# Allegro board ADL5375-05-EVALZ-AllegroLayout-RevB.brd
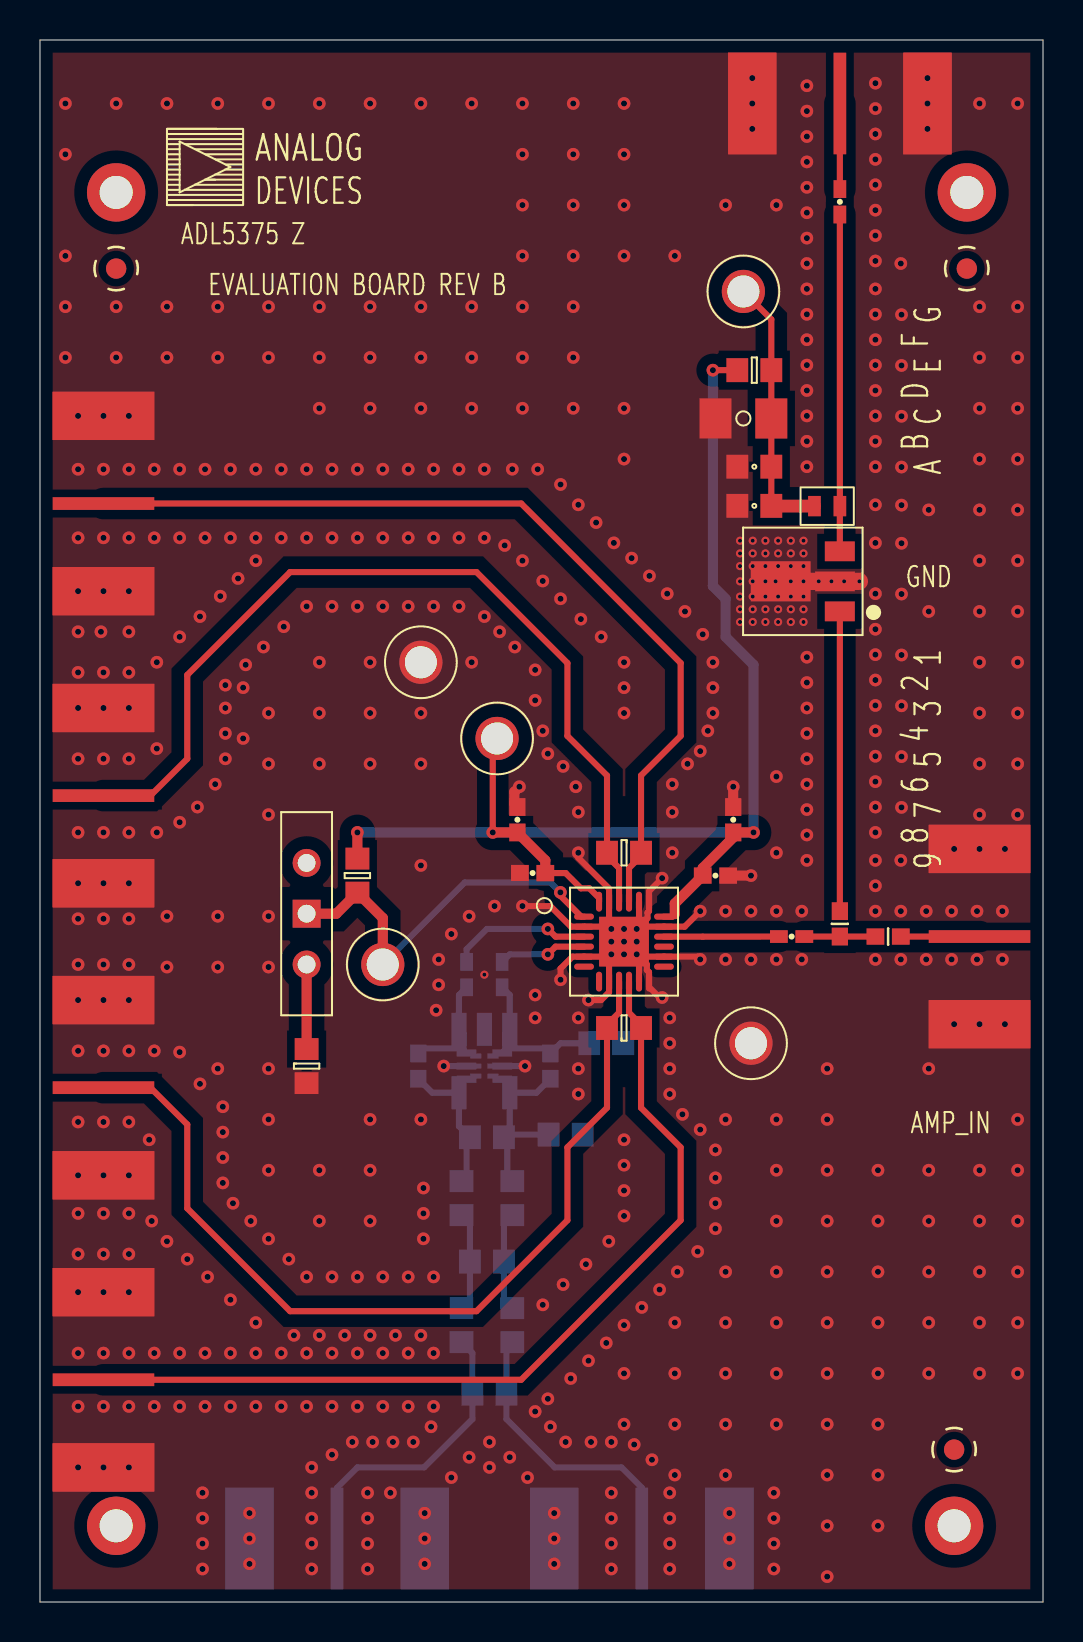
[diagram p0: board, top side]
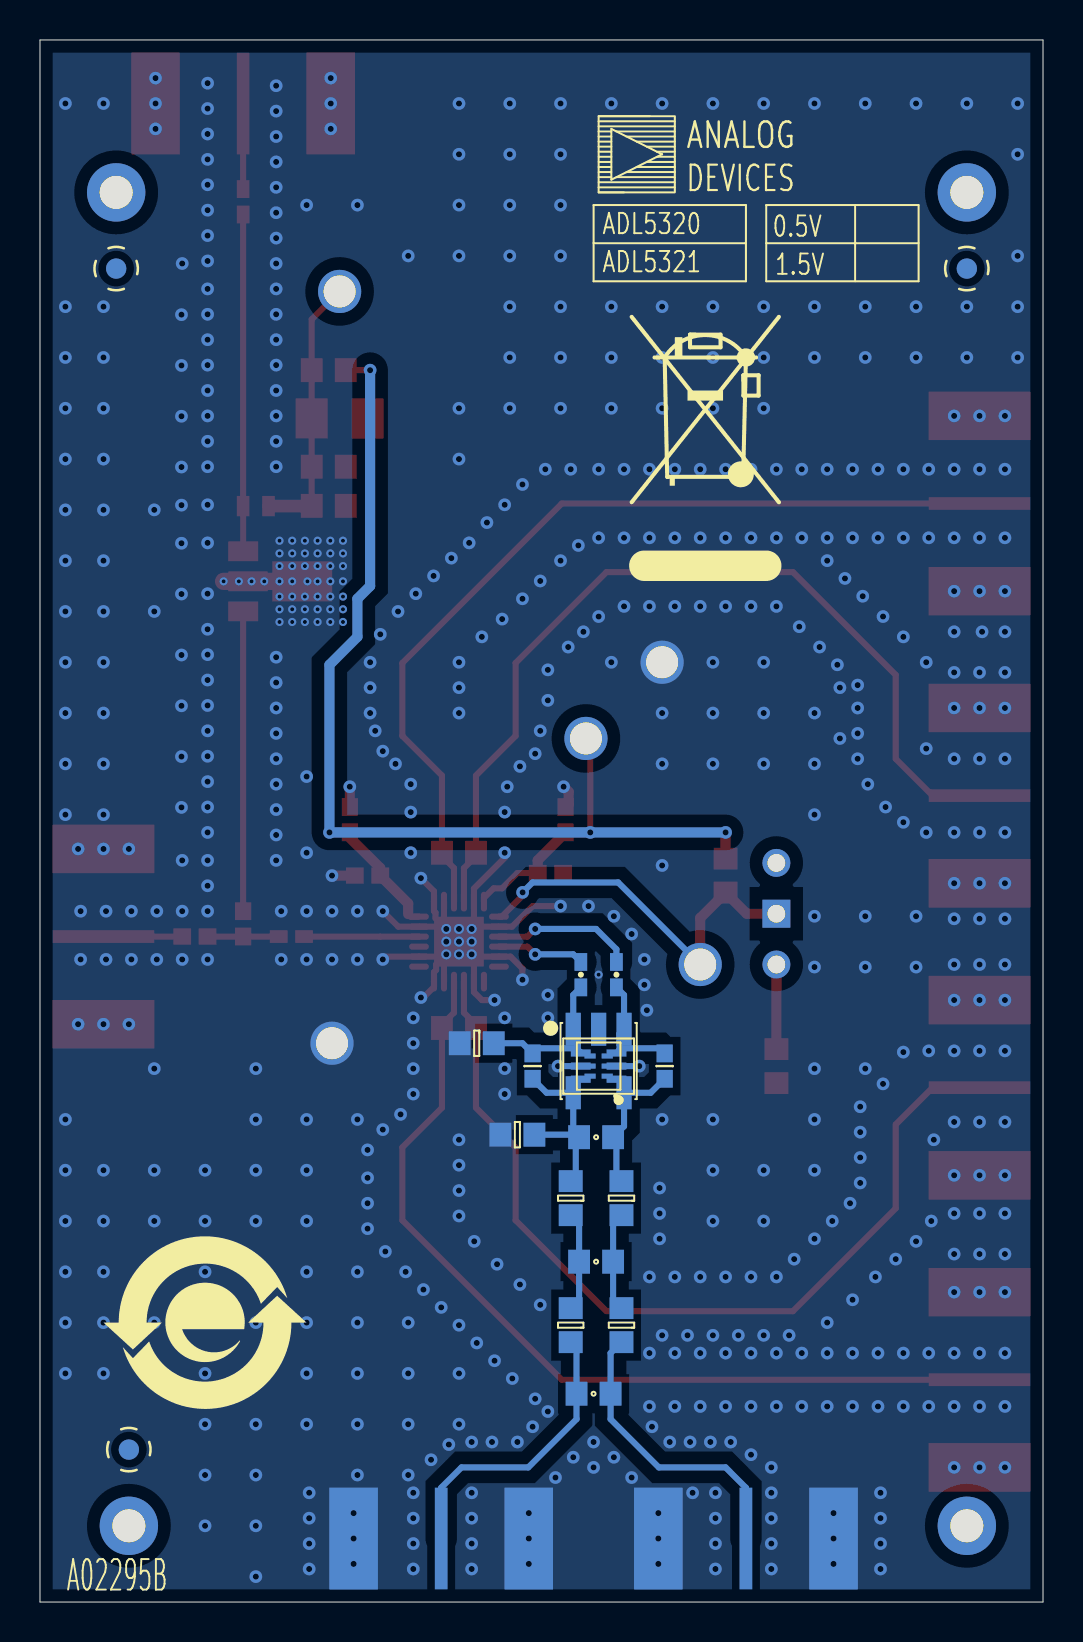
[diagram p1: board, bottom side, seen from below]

Outline 50.16 x 78.11 mm; copper layers: TOP, L2_GND, L3_GND, BOTTOM. Coordinates in mm from the lower left corner of the outline.
Outline path: 0,78.11 50.16,78.11 50.16,0 0,0 0,78.11

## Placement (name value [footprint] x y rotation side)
AMP_OUT  JOHNSON142-0701-851  [CNJOHNSON142-0701-851]  40 75.56 90 top
C1  100pF  [C0402]  37.59 33.27 0 top
C2  100pF  [C0402]  33.78 36.32 0 top
C3  100pF  [C0402]  24.64 36.45 180 top
C4  0.1UF  [C0402]  34.67 39.12 90 top
C5  0.1UF  [C0402]  23.88 39.12 90 top
C6  100pF  [C0402]  21.34 31.37 90 bottom
C7  100pF  [C0402]  23.11 31.37 90 bottom
C9  10UF  [C1206]  35.18 59.18 180 top
C10  10000pF  [C0603]  35.73 56.77 180 top
C11  22PF  [C0603]  35.73 54.81 180 top
C12  22PF  [C0402]  40 70.02 90 top
C16  TBD0603  [C0603]  22.35 23.24 0 bottom
C17  TBD0603  [C0603]  22.35 17.02 0 bottom
C18  TBD0603  [C0603]  22.48 10.41 0 bottom
DSOP  YEL  [CNLOOPTP]  17.15 31.88 90 top
GND  BLK  [CNLOOPTP]  19.05 46.99 0 top
GND1  BLK  [CNLOOPTP]  35.56 27.94 0 top
IBBN  JOHNSON142-0701-851  [CNJOHNSON142-0701-851]  2.54 40.32 180 top
IBBP  JOHNSON142-0701-851  [CNJOHNSON142-0701-851]  2.54 54.93 180 top
L1  15nH  [L7144]  39.37 54.8 180 top
LOIN  JOHNSON142-0701-851  [CNJOHNSON142-0701-851]  30.1 2.54 270 bottom
LOIP  JOHNSON142-0701-851  [CNJOHNSON142-0701-851]  14.86 2.54 270 bottom
MOD_OUT  JOHNSON142-0701-851  [CNJOHNSON142-0701-851]  47.62 33.27 0 top
NOREF  -  []  257.81 -31.75 0 top
NOREF#2  -  []  443.48 -203.84 0 top
NOREF#3  -  [unnamed#2]  3.81 66.67 0 top
NOREF#4  -  []  542.54 -186.06 0 top
NOREF#5  -  []  6.35 69.85 0 top
NOREF#6  -  []  -158.75 -118.11 0 top
NOREF#7  -  [unnamed#2]  45.72 3.81 0 top
NOREF#8  -  []  50.16 0 90 top
NOREF#9  -  [unnamed#2]  45.72 7.62 0 top
NOREF#10  -  []  0 0 0 top
NOREF#11  -  []  -158.75 -118.11 0 top
NOREF#12  -  []  0 78.11 270 top
NOREF#13  -  [unnamed#2]  46.35 66.67 0 top
NOREF#14  -  []  0 0 0 top
NOREF#15  -  []  0 0 90 top
NOREF#16  -  []  0 0 90 top
NOREF#17  -  []  0 0 0 top
NOREF#18  -  [unnamed#2]  3.81 70.48 0 top
NOREF#19  -  []  -171.2 -257.18 0 top
NOREF#20  -  []  192.79 -64.9 0 top
NOREF#21  -  [unnamed#2]  3.81 3.81 0 top
NOREF#22  -  []  26.67 85.09 0 top
NOREF#23  -  []  -41.91 -107.95 0 top
NOREF#24  -  []  50.16 78.11 180 top
NOREF#25  -  [unnamed#2]  46.35 70.48 0 top
NOREF#26  -  [unnamed#2]  46.35 66.67 180 bottom
NOREF#27  -  [unnamed#2]  3.81 66.67 180 bottom
NOREF#28  -  []  7.62 67.95 180 bottom
NOREF#29  -  [unnamed#2]  45.72 7.62 180 bottom
NOREF#30  -  []  22.23 70.48 180 bottom
NOREF#31  -  []  41.91 13.97 180 bottom
QBBN  JOHNSON142-0701-851  [CNJOHNSON142-0701-851]  2.54 25.72 180 top
QBBP  JOHNSON142-0701-851  [CNJOHNSON142-0701-851]  2.54 11.11 180 top
R1  TBD0402  [R0402]  42.42 33.27 0 top
R2  0  [R0402]  40 33.91 90 top
R6  10K  [R0603]  15.88 36.32 270 top
R7  100  [R0603]  29.21 37.47 180 top
R12  100  [R0603]  29.21 28.7 0 top
R13  0  [R0603]  35.73 61.59 180 top
R14  0  [R0603]  21.08 13.84 90 bottom
R15  49.9  [R0603]  13.33 26.8 270 top
R16  TBD0603  [R0603]  23.62 13.84 90 bottom
R17  0  [R0603]  28.32 27.94 0 bottom
R18  0  [R0603]  21.08 20.19 90 bottom
R19  TBD0603  [R0603]  23.62 20.19 90 bottom
R20  TBD0402  [R0402]  25.53 26.8 90 bottom
R21  0  [R0402]  18.92 26.8 90 bottom
R22  TBD0603  [R0603]  26.29 23.37 0 bottom
S1  09-03-201-02  [SWSECMA0903201]  13.33 34.42 90 top
T1  TC1-1-43A+  [AT224-1]  22.23 27.05 180 bottom
T2  3600BL14M050  [T0603-6P]  22.23 26.8 90 bottom
T2A  5400BL15B050E  [XFMR2450BL15B050]  22.23 26.8 90 bottom
U1  ADL5375-05ACPZ-R7  [QFN24_4X4_PAD2_5X2_5]  29.21 33.02 270 top
U2  ADL5320  [SOT-89]  38.15 51.04 90 top
VPOS  RED  [CNLOOPTP]  22.86 43.18 0 top
VPOS_AMP  RED  [CNLOOPTP]  35.18 65.53 0 top

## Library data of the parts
AMP_OUT IBBN IBBP LOIN LOIP MOD_OUT QBBN QBBP = CNBNC5P: User Part Number: UPN; part number: CNBNC5P_SM-JOHNSON142-0701-851,E000923,CNJOHNSON142-0701-851
C1-C3 C6 C7 = CAP: part number: CAP_SM-100PF,50V,5,E007896,C0402; tolerance: 5
C4 C5 = CAP: part number: CAP_SM-0.1UF,16V,10,E007200,C0402; tolerance: 10
C9 = CAP: Tolerance: 10; User Part Number: UPN; part number: CAP_SM-10UF,25V,10,E006874,C1206; tolerance: 10
C10 = CAP: Tolerance: 10; User Part Number: UPN; part number: CAP_SM-10000PF,25V,10,E012078,C0603; tolerance: 10
C11 = CAP: Tolerance: 5; User Part Number: UPN; part number: CAP_SM-22PF,50V,5,E000411,C0603; tolerance: 5
C12 = CAP: part number: CAP_SM-22PF,50V,5,E000265,C0402; tolerance: 5
C16-C18 = CAP: User Part Number: UPN; part number: CAP_SM-TBD0603,TBD0603,TBD0603,E000382,C0603
DSOP = CNTP1P: User Part Number: UPN; part number: CNTP1P_TH-YEL,E000945,CNLOOPTP
GND GND1 = CNTP1P: User Part Number: UPN; part number: CNTP1P_TH-BLK,E000948,CNLOOPTP
L1 = IND: Tolerance: 5; User Part Number: UPN; part number: IND_SM-15NH,5,E010518,L7144; tolerance: 5
R1 R20 = RES: User Part Number: UPN; part number: RES_SM-TBD0402,TBD0402,TBD0402,E004049,R0402
R2 R21 = RES: Tolerance: 5; User Part Number: UPN; part number: RES_SM-0,1/16W,5,E003438,R0402; tolerance: 5
R6 = RES: part number: RES_SM-10K,1/10W,1,E003671,R0603; tolerance: 1
R7 R12 = RES: part number: RES_SM-100,1/10W,1,E003668,R0603; tolerance: 1
R13 R14 R17 R18 = RES: Tolerance: 1; User Part Number: UPN; part number: RES_SM-0,1/16W,1,E004207,R0603; tolerance: 1
R15 = RES: part number: RES_SM-49.9,1/10W,1,E003673,R0603; tolerance: 1
R16 R19 R22 = RES: User Part Number: UPN; part number: RES_SM-TBD0603,TBD0603,TBD0603,E004050,R0603
S1 = SWSECMA: User Part Number: UPN; part number: SWSECMA_TH-09-03-201-02,E004565,SWSECMA0903201
T1 = XFMRETC1_A: User Part Number: UPN; part number: XFMRETC1_A_SM-TC1-1-43A+,E012306,AT224-1
T2 = XFMR3600BL: User Part Number: UPN; part number: XFMR3600BL_SM-3600BL14M050,E007972,T0603-6P
T2A = XFMR3600BL: User Part Number: UPN; part number: XFMR3600BL_SM-5400BL15B050E,E012539,XFMR2450BL15B050
U1 = ADL5375: User Part Number: UPN; part number: ADL5375_SM-ADL5375-05ACPZ-R7,E007336,QFN24_4X4_PAD2_5X2_5
U2 = ADL5320: User Part Number: UPN; part number: ADL5320_SM-ADL5320,E006429,SOT-89
VPOS VPOS_AMP = CNTP1P: User Part Number: UPN; part number: CNTP1P_TH-RED,E000947,CNLOOPTP

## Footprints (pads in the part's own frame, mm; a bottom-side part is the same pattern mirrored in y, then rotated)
AT224-1
  rect 0.762x1.651 smd: 1(-1.27,1.587) 2(0,1.587) 3(1.27,1.587) 4(1.27,-1.587) 6(-1.27,-1.587)
C0402
  rect 0.889x0.813 smd: 1(-0.635,0) 2(0.635,0)
C0603
  rect 1.092x1.194 smd: 1(-0.851,0) 2(0.851,0)
C1206
  rect 1.6x2.007 smd: 1(-1.397,0) 2(1.397,0)
CNJOHNSON142-0701-851
  rect 5.08x0.635 smd: 1(-0.635,0)
  rect 5.08x2.413 smd: 2(-0.635,4.381) 3(-0.635,4.381) 4(-0.635,-4.381) 5(-0.635,-4.381)
CNLOOPTP
  round 2.159 hole 1.6: 1(0,0)
L7144
  rect 0.635x1.016 smd: 1(-0.635,0) 2(0.635,0)
QFN24_4X4_PAD2_5X2_5
  oval 0.305x0.991 smd: 1(-1.25,-1.999) 2(-0.749,-1.999) 3(-0.249,-1.999) 4(0.249,-1.999) 5(0.749,-1.999) 6(1.25,-1.999) 13(1.25,1.999) 14(0.749,1.999) 15(0.249,1.999) 16(-0.249,1.999) 17(-0.749,1.999) 18(-1.25,1.999)
  oval 0.991x0.305 smd: 7(1.999,-1.25) 8(1.999,-0.749) 9(1.999,-0.249) 10(1.999,0.249) 11(1.999,0.749) 12(1.999,1.25) 19(-1.999,1.25) 20(-1.999,0.749) 21(-1.999,0.249) 22(-1.999,-0.249) 23(-1.999,-0.749) 24(-1.999,-1.25)
  rect 2.489x2.489 smd: PAD(0,0)
R0402
  rect 0.889x0.813 smd: 1(-0.635,0) 2(0.635,0)
R0603
  rect 1.092x1.194 smd: 1(-0.851,0) 2(0.851,0)
SOT-89
  rect 0.991x1.499 smd: 1(-1.501,-1.852) 3(1.501,-1.852)
  rect 0.991x1.981 smd: 2(0,-1.61)
  rect 2.007x2.997 smd: 4(0,1.102)
SWSECMA0903201
  rect 1.397x1.397 hole 0.889: 1(0,0)
  round 1.397 hole 0.889: 2(-2.54,0) 3(2.54,0)
T0603-6P
  rect 0.254x0.559 smd: 1(-0.503,-0.429) 2(0,-0.429) 3(0.503,-0.429) 4(0.503,0.429) 5(0,0.429) 6(-0.503,0.429)
unnamed#2
  round 1.016 smd: (0,0)
XFMR2450BL15B050
  rect 0.356x0.991 smd: 1(-0.655,-0.894) 2(0,-0.894) 3(0.655,-0.894) 4(0.655,0.894) 5(0,0.894) 6(-0.655,0.894)

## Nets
AGND: AMP_OUT.2(SH1) AMP_OUT.3(SH2) AMP_OUT.4(SH3) AMP_OUT.5(SH4) C2.2(N2) C3.2(N2) C4.2(N2) C5.2(N2) C9.2(N2) C10.2(N2) C11.2(N2) GND.1(N1) GND1.1(N1) IBBN.2(SH1) IBBN.3(SH2) IBBN.4(SH3) IBBN.5(SH4) IBBP.2(SH1) IBBP.3(SH2) IBBP.4(SH3) IBBP.5(SH4) LOIN.2(SH1) LOIN.3(SH2) LOIN.4(SH3) LOIN.5(SH4) LOIP.2(SH1) LOIP.3(SH2) LOIP.4(SH3) LOIP.5(SH4) MOD_OUT.2(SH1) MOD_OUT.3(SH2) MOD_OUT.4(SH3) MOD_OUT.5(SH4) QBBN.2(SH1) QBBN.3(SH2) QBBN.4(SH3) QBBN.5(SH4) QBBP.2(SH1) QBBP.3(SH2) QBBP.4(SH3) QBBP.5(SH4) R15.2(N2) R17.2(N2) R22.2(N2) T2.2(GND_DC_FEED_RFGND) T2.5(GND) T2A.2(GND_DC_FEED_RFGND) T2A.5(GND) U1.2(COMM1) U1.5(COMM2) U1.8(COMM3) U1.11(COMM4) U1.12(COMM5) U1.14(COMM6) U1.17(COMM7) U1.19(COMM8) U1.20(COMM9) U1.23(COMM10) U1.PAD U2.2(GND) U2.4(GND1)
P1: C16.1(N1) R18.2(N2) R21.1(N1) T1.4(N3) T2.1(UNBAL_IN) T2A.1(UNBAL_IN)
P3: C6.1(N1) R21.2(N2) T1.3(N2) T2.3(BAL_OUT1) T2A.3(BAL_OUT1)
P4: C7.1(N1) R17.1(N1) R20.2(N2) T1.1(N1) T2.4(BAL_OUT2) T2A.4(BAL_OUT2)
P6: C16.2(N2) R19.2(N2) R20.1(N1) R22.1(N1) T1.6(N4) T2.6(NC_6) T2A.6(NC_6)
UNNAMED_1_ADL5320_I149_RFIN: R2.2(N2) U2.1(RFIN)
UNNAMED_1_ADL5320_I149_RFOUT: C12.1(N1) L1.1(N1) U2.3(RFOUT)
UNNAMED_1_ADL5375_I86_DSOP: DSOP.1(N1) R6.2(N2) S1.1(C) U1.1(DSOP)
UNNAMED_1_ADL5375_I86_IBBN: IBBN.1(CNTR) R7.2(N2) U1.22(IBBN)
UNNAMED_1_ADL5375_I86_IBBP: IBBP.1(CNTR) R7.1(N1) U1.21(IBBP)
UNNAMED_1_ADL5375_I86_LOIN: C7.2(N2) U1.4(LOIN)
UNNAMED_1_ADL5375_I86_LOIP: C6.2(N2) U1.3(LOIP)
UNNAMED_1_ADL5375_I86_QBBN: QBBN.1(CNTR) R12.1(N1) U1.9(QBBN)
UNNAMED_1_ADL5375_I86_QBBP: QBBP.1(CNTR) R12.2(N2) U1.10(QBBP)
UNNAMED_1_ADL5375_I86_RFOUT: C1.1(N1) U1.16(RFOUT)
UNNAMED_1_CAP_I212_N2: AMP_OUT.1(CNTR) C12.2(N2)
UNNAMED_1_CAP_I217_N1: C9.1(N1) C10.1(N1) C11.1(N1) L1.2(N2) R13.1(N1) VPOS_AMP.1(N1)
UNNAMED_1_CAP_I246_N1: C17.1(N1) R14.2(N2) R18.1(N1)
UNNAMED_1_CAP_I246_N2: C17.2(N2) R16.2(N2) R19.1(N1)
UNNAMED_1_CAP_I262_N2: C1.2(N2) R1.1(N1) R2.1(N1)
UNNAMED_1_CNBNC5P_I117_CNTR: MOD_OUT.1(CNTR) R1.2(N2)
UNNAMED_1_CNBNC5P_I202_CNTR: C18.1(N1) LOIP.1(CNTR) R14.1(N1)
UNNAMED_1_CNBNC5P_I203_CNTR: C18.2(N2) LOIN.1(CNTR) R16.1(N1)
UNNAMED_1_RES_I276_N1: R15.1(N1) S1.2(NO)
VPOS: C2.1(N1) C3.1(N1) C4.1(N1) C5.1(N1) R6.1(N1) R13.2(N2) U1.18(VPS1) U1.24(VPS2) VPOS.1(N1)

Pads without a net: S1 3; T1 2; U1 6 7 13 15

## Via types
v1: diameter 0.635, hole 0.305, TOP to BOTTOM, 600 vias
v2: diameter 0.406, hole 0.203, TOP to BOTTOM, 47 vias
v3: diameter 0.508, hole 0.305, TOP to BOTTOM, 9 vias

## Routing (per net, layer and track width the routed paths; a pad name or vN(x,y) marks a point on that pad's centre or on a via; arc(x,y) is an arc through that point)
AGND: length 43
  TOP w0.305: 28.46,32.27 v3(28.57,32.38) v3(29.21,33.02) ; 28.46,32.27 U1.5 26.63,32.27 26.03,31.67 v1(26.03,31.11) ; 28.46,32.27 U1.8 28.46,30.5 28.06,30.1 v1(27.43,30.1) ; 29.96,32.27 U1.14 32.88,32.27 v1(33.02,32.13) ; 29.96,32.27 30.35,31.88 30.35,31.6 30.46,31.49 U1.12 30.46,30.75 30.99,30.23 v1(31.12,30.23) ; 29.96,32.27 v3(29.84,32.38) v3(29.21,33.02) ; 29.96,32.27 U1.11 ; U1.20 29.96,33.77 ; 29.96,33.77 v3(29.84,33.66) v3(29.21,33.02) ; 29.96,33.77 U1.17 32.25,33.77 v1(33.02,34.54) ; 29.96,33.77 30.38,34.19 30.38,34.47 30.46,34.55 U1.19 30.46,35.54 v1(31.12,36.2) ; v1(26.92,37.47) 26.92,37.21 28.46,35.67 U1.23 28.46,33.77 ; v3(29.21,33.02) v3(28.57,33.66) 28.46,33.77 ; 28.46,33.77 U1.2 26.56,33.77 25.53,34.8 v1(24.13,34.8)
  TOP w0.508: v1(35.56,36.32) 34.35,36.32 ; v1(23.98,40.77) 23.72,40.51 23.72,39.9 C5.2 ; C4.2 v1(34.67,40.77)
  TOP w0.864: v2(37.55,51.04) U2.4 ; v2(40.98,51.04) v2(40.22,51.04) U2.2 v2(39.58,51.04) v2(38.95,51.04) v2(38.19,51.04)
  BOTTOM w0.305: T2A.5 v1(24.26,26.8) ; T2A.2 v1(20.19,26.8)
  vias: v1(1.27,74.93) v1(1.27,72.39) v1(1.27,67.31) v1(1.27,64.77) v1(1.27,62.23) v1(1.91,59.31) v1(1.91,56.64) v1(1.91,53.21) v1(1.91,50.55) v1(1.91,48.51) v1(1.91,46.48) v1(1.91,44.7) v1(1.91,42.16) v1(1.91,38.48) v1(1.91,35.94) v1(1.91,34.16) v1(1.91,31.88) v1(1.91,30.1) v1(1.91,27.56) v1(1.91,24) v1(1.91,21.34) v1(1.91,19.43) v1(1.91,17.4) v1(1.91,15.49) v1(1.91,12.45) v1(1.91,9.78) v1(1.91,6.73) v1(3.05,48.51) v1(3.18,59.31) v1(3.18,56.64) v1(3.18,53.21) v1(3.18,50.55) v1(3.18,46.48) v1(3.18,44.7) v1(3.18,42.16) v1(3.18,38.48) v1(3.18,35.94) v1(3.18,34.16) v1(3.18,31.88) v1(3.18,30.1) v1(3.18,27.56) v1(3.18,24) v1(3.18,21.34) v1(3.18,19.43) v1(3.18,17.4) v1(3.18,15.49) v1(3.18,12.45) v1(3.18,9.78) v1(3.18,6.73) v1(3.81,74.93) v1(3.81,64.77) v1(3.81,62.23) v1(4.45,59.31) v1(4.45,56.64) v1(4.45,53.21) v1(4.45,50.55) v1(4.45,48.51) v1(4.45,46.48) v1(4.45,44.7) v1(4.45,42.16) v1(4.45,38.48) v1(4.45,35.94) v1(4.45,34.16) v1(4.45,31.88) v1(4.45,30.1) v1(4.45,27.56) v1(4.45,24) v1(4.45,21.34) v1(4.45,19.43) v1(4.45,17.4) v1(4.45,15.49) v1(4.45,12.45) v1(4.45,9.78) v1(4.45,6.73) v1(5.46,23.11) v1(5.59,19.05) v1(5.71,56.64) v1(5.71,53.21) v1(5.71,27.56) v1(5.71,12.45) v1(5.71,9.78) v1(5.84,46.99) v1(5.84,42.67) v1(5.84,38.48) v1(6.35,74.93) v1(6.35,64.77) v1(6.35,62.23) v1(6.35,34.29) v1(6.35,31.75) v1(6.35,18.03) v1(6.99,56.64) v1(6.99,53.21) v1(6.99,48.26) v1(6.99,38.99) v1(6.99,27.5) v1(6.99,12.45) v1(6.99,9.78) v1(7.37,17.14) v1(7.87,39.75) v1(8,49.28) v1(8,25.91) v1(8.13,5.46) v1(8.13,4.19) v1(8.13,2.92) v1(8.13,1.65) v1(8.26,56.64) v1(8.26,53.21) v1(8.26,12.45) v1(8.26,9.78) v1(8.38,16.26) v1(8.76,40.89) v1(8.89,74.93) v1(8.89,64.77) v1(8.89,62.23) v1(8.89,34.29) v1(8.89,31.75) v1(8.89,26.67) v1(9.02,50.29) v1(9.14,24.76) v1(9.14,23.49) v1(9.14,22.22) v1(9.14,20.95) v1(9.27,45.85) v1(9.27,44.7) v1(9.27,43.43) v1(9.27,42.16) v1(9.53,56.64) v1(9.53,53.21) v1(9.53,15.11) v1(9.53,12.45) v1(9.53,9.78) v1(9.65,19.94) v1(9.91,51.18) v1(10.16,45.72) v1(10.16,43.18) v1(10.29,46.86) v1(10.48,4.45) v1(10.48,3.17) v1(10.48,1.91) v1(10.54,19.05) v1(10.79,56.64) v1(10.79,53.21) v1(10.79,52.07) v1(10.79,13.97) v1(10.79,12.45) v1(10.79,9.78) v1(11.18,47.75) v1(11.43,74.93) v1(11.43,64.77) v1(11.43,62.23) v1(11.43,44.45) v1(11.43,41.91) v1(11.43,39.37) v1(11.43,34.29) v1(11.43,31.75) v1(11.43,26.67) v1(11.43,24.13) v1(11.43,21.59) v1(11.43,18.16) v1(12.06,56.64) v1(12.06,53.21) v1(12.06,12.45) v1(12.06,9.78) v1(12.19,48.77) v1(12.45,17.14) v1(12.7,13.34) v1(13.33,56.64) v1(13.33,53.21) v1(13.33,49.78) v1(13.33,16.26) v1(13.33,12.45) v1(13.33,9.78) v1(13.59,6.73) v1(13.59,5.46) v1(13.59,4.19) v1(13.59,2.92) v1(13.59,1.65) v1(13.97,74.93) v1(13.97,64.77) v1(13.97,62.23) v1(13.97,59.69) v1(13.97,46.99) v1(13.97,44.45) v1(13.97,41.91) v1(13.97,21.59) v1(13.97,19.05) v1(13.97,13.34) v1(14.6,56.64) v1(14.6,53.21) v1(14.6,49.78) v1(14.6,16.26) v1(14.6,12.45) v1(14.6,9.78) v1(14.6,7.37) v1(15.24,13.34) v1(15.62,8) v1(15.88,56.64) v1(15.88,53.21) v1(15.88,49.78) v1(15.88,16.26) v1(15.88,12.45) v1(15.88,9.78) v1(16.38,5.46) v1(16.38,4.19) v1(16.38,2.92) v1(16.38,1.65) v1(16.51,74.93) v1(16.51,64.77) v1(16.51,62.23) v1(16.51,59.69) v1(16.51,46.99) v1(16.51,44.45) v1(16.51,41.91) v1(16.51,24.13) v1(16.51,21.59) v1(16.51,19.05) v1(16.51,13.34) v1(16.64,8) v1(17.15,56.64) v1(17.15,53.21) v1(17.15,49.78) v1(17.15,16.26) v1(17.15,12.45) v1(17.15,9.78) v1(17.53,5.46) v1(17.65,8) v1(17.78,13.34) v1(18.41,56.64) v1(18.41,53.21) v1(18.41,49.78) v1(18.41,16.26) v1(18.41,12.45) v1(18.41,9.78) v1(18.67,8) v1(19.05,74.93) v1(19.05,64.77) v1(19.05,62.23) v1(19.05,59.69) v1(19.05,44.45) v1(19.05,41.91) v1(19.05,36.83) v1(19.05,24.13) v1(19.05,13.34) v1(19.18,20.7) v1(19.18,19.43) v1(19.18,18.16) v1(19.24,4.45) v1(19.24,3.17) v1(19.24,1.91) v1(19.56,8.76) v1(19.69,56.64) v1(19.69,53.21) v1(19.69,49.78) v1(19.69,16.26) v1(19.69,12.45) v1(19.69,9.78) v1(19.81,29.59) v1(19.94,32.13) v1(19.94,30.86) v1(20.57,33.4) v1(20.57,6.22) v1(20.95,56.64) v1(20.95,53.21) v1(20.95,49.78) v1(21.46,34.29) v1(21.46,7.24) v1(21.59,74.93) v1(21.59,64.77) v1(21.59,62.23) v1(21.59,59.69) v1(21.59,46.99) v1(22.23,56.64) v1(22.23,53.21) v1(22.23,49.28) v1(22.48,8) v1(22.48,6.73) v1(22.73,34.8) v1(22.99,48.51) v1(23.24,52.83) v1(23.49,7.24) v1(23.62,56.64) v1(23.75,47.75) v1(24.13,74.93) v1(24.13,72.39) v1(24.13,69.85) v1(24.13,67.31) v1(24.13,64.77) v1(24.13,62.23) v1(24.13,59.69) v1(24.13,52.07) v1(24.38,6.22) v1(24.77,46.61) v1(24.77,45.09) v1(24.77,30.35) v1(24.77,29.21) v1(24.77,9.53) v1(24.89,56.64) v1(25.15,51.05) v1(25.15,43.56) v1(25.15,14.86) v1(25.4,42.42) v1(25.4,10.16) v1(25.53,8.76) v1(25.72,4.45) v1(25.72,3.17) v1(25.72,1.91) v1(26.03,55.88) v1(26.03,50.16) v1(26.16,41.78) v1(26.16,15.88) v1(26.29,8) v1(26.54,11.18) v1(26.67,74.93) v1(26.67,72.39) v1(26.67,69.85) v1(26.67,67.31) v1(26.67,64.77) v1(26.67,62.23) v1(26.67,59.69) v1(26.8,40.77) v1(26.92,54.86) v1(26.92,39.5) v1(26.92,29.21) v1(26.92,26.67) v1(26.92,25.4) v1(27.05,49.15) v1(27.3,16.89) v1(27.43,12.07) v1(27.56,8) v1(27.81,53.98) v1(28.07,48.26) v1(28.32,12.95) v1(28.45,18.03) v1(28.57,8) v1(28.57,5.46) v1(28.57,4.19) v1(28.57,2.92) v1(28.57,1.65) v1(28.7,52.96) v1(29.21,74.93) v1(29.21,72.39) v1(29.21,69.85) v1(29.21,67.31) v1(29.21,59.69) v1(29.21,57.15) v1(29.21,46.99) v1(29.21,45.72) v1(29.21,44.45) v1(29.21,23.11) v1(29.21,21.84) v1(29.21,20.57) v1(29.21,19.3) v1(29.21,13.84) v1(29.21,11.43) v1(29.21,8.89) v1(29.59,52.2) v1(29.72,7.87) v1(30.1,14.73) v1(30.48,51.31) v1(30.61,7.11) v1(30.99,15.62) v1(31.37,50.42) v1(31.5,29.21) v1(31.5,27.94) v1(31.5,26.67) v1(31.5,25.4) v1(31.5,5.46) v1(31.5,4.19) v1(31.5,2.92) v1(31.5,1.65) v1(31.62,40.89) v1(31.62,39.5) v1(31.62,37.47) v1(31.75,67.31) v1(31.75,13.97) v1(31.75,11.43) v1(31.75,8.89) v1(31.75,6.35) v1(31.88,16.51) v1(32.13,24.38) v1(32.26,49.53) v1(32.38,41.91) v1(32.89,17.53) v1(33.02,42.55) v1(33.02,23.62) v1(33.15,48.39) v1(33.4,43.56) v1(33.66,46.99) v1(33.66,45.72) v1(33.66,44.45) v1(33.78,22.61) v1(33.78,21.21) v1(33.78,19.94) v1(33.78,18.67) v1(34.29,69.85) v1(34.29,34.54) v1(34.29,32.13) v1(34.29,24.13) v1(34.29,16.51) v1(34.29,13.97) v1(34.29,11.43) v1(34.29,8.89) v1(34.29,6.35) v1(34.48,4.45) v1(34.48,3.17) v1(34.48,1.91) v1(35.56,34.54) v1(35.56,32.13) v1(35.62,76.2) v1(35.62,74.93) v1(35.62,73.66) v1(36.7,5.46) v1(36.7,4.19) v1(36.7,2.92) v1(36.7,1.65) v1(36.83,69.85) v1(36.83,41.28) v1(36.83,37.47) v1(36.83,34.54) v1(36.83,32.13) v1(36.83,24.13) v1(36.83,21.59) v1(36.83,19.05) v1(36.83,16.51) v1(36.83,13.97) v1(36.83,11.43) v1(36.83,8.89) v1(38.1,34.54) v1(38.1,32.13) v1(38.35,75.82) v1(38.35,74.55) v1(38.35,73.28) v1(38.35,72.01) v1(38.35,70.74) v1(38.35,69.47) v1(38.35,68.2) v1(38.35,66.93) v1(38.35,65.66) v1(38.35,64.39) v1(38.35,63.12) v1(38.35,61.85) v1(38.35,60.58) v1(38.35,59.31) v1(38.35,58.04) v1(38.35,56.77) v1(38.35,47.24) v1(38.35,45.97) v1(38.35,44.7) v1(38.35,43.43) v1(38.35,42.16) v1(38.35,40.89) v1(38.35,39.62) v1(38.35,38.35) v1(38.35,37.08) v1(39.37,26.67) v1(39.37,24.13) v1(39.37,21.59) v1(39.37,19.05) v1(39.37,16.51) v1(39.37,13.97) v1(39.37,11.43) v1(39.37,8.89) v1(39.37,6.35) v1(39.37,3.81) v1(39.37,1.27) v1(41.78,75.95) v1(41.78,74.68) v1(41.78,73.41) v1(41.78,72.14) v1(41.78,70.87) v1(41.78,69.6) v1(41.78,68.33) v1(41.78,67.06) v1(41.78,65.66) v1(41.78,64.39) v1(41.78,63.12) v1(41.78,61.85) v1(41.78,60.58) v1(41.78,59.31) v1(41.78,58.04) v1(41.78,56.77) v1(41.78,54.86) v1(41.78,52.96) v1(41.78,50.42) v1(41.78,48.64) v1(41.78,47.37) v1(41.78,46.1) v1(41.78,44.83) v1(41.78,43.56) v1(41.78,42.29) v1(41.78,41.02) v1(41.78,39.75) v1(41.78,38.48) v1(41.78,37.08) v1(41.78,35.81) v1(41.78,34.54) v1(41.78,32.13) v1(41.91,21.59) v1(41.91,19.05) v1(41.91,16.51) v1(41.91,13.97) v1(41.91,11.43) v1(41.91,8.89) v1(41.91,6.35) v1(41.91,3.81) v1(43.05,66.93) v1(43.09,64.37) v1(43.09,61.83) v1(43.09,59.29) v1(43.09,56.75) v1(43.09,54.85) v1(43.09,52.94) v1(43.09,50.4) v1(43.09,47.35) v1(43.09,44.81) v1(43.09,42.27) v1(43.09,39.73) v1(43.05,37.08) v1(43.05,34.54) v1(43.05,32.13) v1(44.39,76.2) v1(44.39,74.93) v1(44.39,73.66) v1(44.32,34.54) v1(44.32,32.13) v1(44.45,54.61) v1(44.45,49.53) v1(44.45,26.67) v1(44.45,21.59) v1(44.45,19.05) v1(44.45,16.51) v1(44.45,13.97) v1(44.45,11.43) v1(45.59,34.54) v1(45.59,32.13) v1(45.72,37.66) v1(45.72,28.89) v1(46.86,34.54) v1(46.86,32.13) v1(46.99,74.93) v1(46.99,64.77) v1(46.99,62.23) v1(46.99,59.69) v1(46.99,57.15) v1(46.99,54.61) v1(46.99,52.07) v1(46.99,49.53) v1(46.99,46.99) v1(46.99,44.45) v1(46.99,41.91) v1(46.99,39.37) v1(46.99,37.66) v1(46.99,28.89) v1(46.99,21.59) v1(46.99,19.05) v1(46.99,16.51) v1(46.99,13.97) v1(46.99,11.43) v1(48.13,34.54) v1(48.13,32.13) v1(48.26,37.66) v1(48.26,28.89) v1(48.89,74.93) v1(48.89,64.77) v1(48.89,62.23) v1(48.89,59.69) v1(48.89,57.15) v1(48.89,54.61) v1(48.89,52.07) v1(48.89,49.53) v1(48.89,46.99) v1(48.89,44.45) v1(48.89,41.91) v1(48.89,39.37) v1(48.89,24.13) v1(48.89,21.59) v1(48.89,19.05) v1(48.89,16.51) v1(48.89,13.97) v1(48.89,11.43) v2(22.23,31.37) v2(35.01,53.07) v2(35.01,52.43) v2(35.01,51.8) v2(35.01,51.04) v2(35.01,50.27) v2(35.01,49.64) v2(35.01,49) v2(35.65,53.07) v2(35.65,52.43) v2(35.65,51.8) v2(35.65,51.04) v2(35.65,50.27) v2(35.65,49.64) v2(35.65,49) v2(36.28,53.07) v2(36.28,52.43) v2(36.28,51.8) v2(36.28,51.04) v2(36.28,50.27) v2(36.28,49.64) v2(36.28,49) v2(36.79,51.04) v2(36.92,53.07) v2(36.92,52.43) v2(36.92,51.8) v2(36.92,50.27) v2(36.92,49.64) v2(36.92,49) v2(37.55,53.07) v2(37.55,52.43) v2(37.55,51.8) v2(37.55,50.27) v2(37.55,49.64) v2(37.55,49) v2(38.19,53.07) v2(38.19,52.43) v2(38.19,51.8) v2(38.19,50.27) v2(38.19,49.64) v2(38.19,49) v3(28.57,33.02) v3(29.21,33.66) v3(29.21,32.38) v3(29.84,33.02)
P1: length 7.1
  BOTTOM w0.305: R18.2 21.34,21.3 21.34,23.08 C16.1 20.95,23.79 T1.4 19.62,25.46 R21.1
P3: length 6
  BOTTOM w0.305: C6.1 20.95,30.35 T1.3 21.18,28.41 21.18,27.6 ; 21.18,27.6 21.1,27.69 19.18,27.69 R21.2 ; 21.18,27.6 T2A.3
P4: length 8.4
  BOTTOM w0.305: 23.12,27.47 T2A.4 ; 23.12,27.47 23.14,27.47 23.35,27.69 25.27,27.69 R20.2 26.03,27.94 R17.1 ; 23.12,27.47 23.27,27.62 23.27,28.41 T1.1 23.49,30.35 C7.1
P6: length 9.1
  BOTTOM w0.305: R19.2 23.37,21.3 23.37,23.08 C16.2 ; R20.1 24.83,25.46 T1.6 23.49,23.53 23.33,23.37 R22.1
  BOTTOM w0.635: 23.33,23.37 C16.2
UNNAMED_1_ADL5320_I149_RFIN: length 15
  TOP w0.305: R2.2 40,49.53 U2.1
UNNAMED_1_ADL5320_I149_RFOUT: length 16.8
  TOP w0.305: U2.3 40,54.54 L1.1 C12.1
UNNAMED_1_ADL5375_I86_DSOP: length 19.7
  TOP w0.305: v1(26.03,35.48) 26.03,35.31 27.07,34.27 U1.1
  TOP w0.508: DSOP.1 17.15,34.2 R6.2 14.82,34.42 S1.1
  BOTTOM w0.305: DSOP.1 21.25,35.98 25.53,35.98 v1(26.03,35.48)
UNNAMED_1_ADL5375_I86_IBBN: length 45.2
  TOP w0.305: U1.22 28.96,36.7 28.36,37.3 R7.2 28.36,41.33 26.38,43.31 26.38,46.95 21.83,51.5 12.51,51.5 7.37,46.36 7.37,42.16 5.52,40.32 IBBN.1
UNNAMED_1_ADL5375_I86_IBBP: length 45.2
  TOP w0.305: IBBP.1 24.07,54.93 32.04,46.95 32.04,43.31 30.06,41.33 R7.1 30.06,37.3 29.46,36.7 U1.21
UNNAMED_1_ADL5375_I86_LOIN: length 4.4
  TOP w0.305: U1.4 25.79,32.77 v1(25.4,32.38)
  BOTTOM w0.305: v1(25.4,32.38) 23.49,32.38 C7.2
UNNAMED_1_ADL5375_I86_LOIP: length 7.1
  TOP w0.305: v1(25.4,33.66) 25.79,33.27 U1.3
  BOTTOM w0.305: C6.2 21.34,32.64 22.35,33.66 v1(25.4,33.66)
UNNAMED_1_ADL5375_I86_QBBN: length 45.2
  TOP w0.305: QBBN.1 5.52,25.72 7.37,23.88 7.37,19.68 12.51,14.54 21.83,14.54 26.38,19.09 26.38,22.73 28.36,24.71 R12.1 28.36,28.87 28.96,29.47 U1.9
UNNAMED_1_ADL5375_I86_QBBP: length 45.2
  TOP w0.305: QBBP.1 24.07,11.11 32.04,19.09 32.04,22.73 30.06,24.71 R12.2 30.06,28.87 29.46,29.47 U1.10
UNNAMED_1_ADL5375_I86_RFOUT: length 5.7
  TOP w0.305: C1.1 33.14,33.27 U1.16
UNNAMED_1_CAP_I212_N2: length 4.3
  TOP w0.305: C12.2 AMP_OUT.1
UNNAMED_1_CAP_I217_N1: length 13.5
  TOP w0.305: VPOS_AMP.1 36.58,64.14 R13.1 C9.1 C10.1 C11.1
  TOP w0.635: C11.1 36.59,54.8 L1.2
UNNAMED_1_CAP_I246_N1: length 5
  BOTTOM w0.305: R14.2 21.5,15.11 C17.1 21.5,18.92 R18.1
UNNAMED_1_CAP_I246_N2: length 5
  BOTTOM w0.305: R16.2 23.2,15.11 C17.2 23.2,18.92 R19.1
UNNAMED_1_CAP_I262_N2: length 3.6
  TOP w0.305: C1.2 R2.1 R1.1
UNNAMED_1_CNBNC5P_I117_CNTR: length 3.9
  TOP w0.305: R1.2 MOD_OUT.1
UNNAMED_1_CNBNC5P_I202_CNTR: length 14.8
  BOTTOM w0.305: LOIP.1 14.86,5.71 15.88,6.73 19.22,6.73 21.63,9.14 C18.1 21.63,12.45 R14.1
UNNAMED_1_CNBNC5P_I203_CNTR: length 14.7
  BOTTOM w0.305: LOIN.1 30.1,5.71 29.08,6.73 25.74,6.73 23.33,9.14 C18.2 23.33,12.7 R16.1
UNNAMED_1_RES_I276_N1: length 4.2
  TOP w0.508: R15.1 S1.2
VPOS: length 65.2
  TOP w0.305: 31.75,34.4 31.62,34.27 U1.18 ; R13.2 v1(33.66,61.59) ; C3.1 26.29,36.45 27.05,35.69 27.48,35.69 27.96,35.2 U1.24 ; v1(22.64,38.48) 22.64,42.96 VPOS.1
  TOP w0.508: C3.1 25.27,37.08 C5.1 v1(22.64,38.48) ; v1(15.88,38.48) R6.1 ; v1(35.69,38.48) C4.1 34.67,38.23 33.15,36.7 C2.1 31.75,34.92 31.75,34.4
  BOTTOM w0.508: v1(33.66,61.59) 33.66,50.8 34.29,50.16 34.29,48.26 35.69,46.86 v1(35.69,38.48) v1(22.64,38.48) v1(15.88,38.48)

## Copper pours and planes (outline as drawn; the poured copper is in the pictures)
AGND on L2_GND (solid shape): 49.53,0.64 0.64,0.64 0.64,77.47 49.53,77.47
AGND on L3_GND (solid shape): 49.53,0.64 0.64,0.64 0.64,77.47 49.53,77.47
AGND on TOP: 0.64,0.64 0.64,77.47 49.53,77.47 49.53,0.64 ; 2 cut-outs
AGND on BOTTOM: 0.64,0.64 0.64,77.47 49.53,77.47 49.53,0.64 ; 3 cut-outs

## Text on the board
Ref Des/Silkscreen Bottom: 1.5V | 0.5V | ADL5320 | ADL5321 | A02295B
User.Comments: T.HA | L.NERETTE | 12JUL10 | 24355
Ref Des/Silkscreen Top: ADL5375 Z | EVALUATION BOARD REV B | GND | AMP_IN | F | D | B | 2 | 4 | 6 | 8 | G | E | C | A | 1 | 3 | 5 | 7 | 9
DIMENSION: (AIR GAP TO GROUND FILL: 0.025") | SEE NOTE 15 | MAX DIA
User.10: L2 GND | 08-      -07
User.11: L3 GND | 08-      -08
User.12: 100 MICRO INCHES NICKEL/ | 2-8 MICRO INCHES GOLD | 16.    SHIP BOARD PALLETIZED FOR ASSEMBLY BY COLONIAL. | RETURN PALLETIZED PASTEMASK ARTWORK TO ANALOG (PRIMARY AND SECONDARY).
User.15: T.HA | L.NERETTE | 12JUL10 | 24355
User.42: FIGURE | SIZE | 8.0 | 12.0 | 35.0 | 63.0 | 65.0 | PLATED | NON-PLATED | FINISHED HOLES IN MILS | ALL UNITS ARE IN MILS | QTY | 47 | 600 | 9 | 3 | 5 | 4 | TOLERANCE/NOTES
